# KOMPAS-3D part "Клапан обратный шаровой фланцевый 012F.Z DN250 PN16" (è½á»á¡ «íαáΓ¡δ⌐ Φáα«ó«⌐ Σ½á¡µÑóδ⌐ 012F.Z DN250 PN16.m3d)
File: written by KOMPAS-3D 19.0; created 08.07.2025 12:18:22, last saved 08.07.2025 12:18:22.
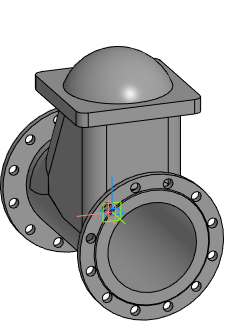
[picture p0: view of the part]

Document properties: Полное имя файла: E:\Dendor Работа Сачек\3D для проектировщиков\5.3 Тип 012F, 012F.Z Клапан обратный шаровой фланцевый\stp_Клапан обратный шаровой фланцевый 012F.Z PN10_16\Клапан обратный шаровой фланцевый 012F.Z DN250 PN16.m3d

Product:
- Part/product: Клапан обратный шаровой фланцевый 012F.Z DN250 PN16

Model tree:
1. Операция без истории:1  (labels: Клапан обратный шаровой фланцевый 012F.Z DN250 PN16)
